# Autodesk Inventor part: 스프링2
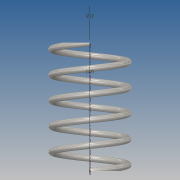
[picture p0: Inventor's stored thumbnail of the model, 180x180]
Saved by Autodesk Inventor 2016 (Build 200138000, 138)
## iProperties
Created: 2016-01
Part Number: 스프링2
Material: 스테인레스 스틸
Document SubType Name: Modeling
Designer: Administrator
Density: 8 g/cm^3
Appearance: 반연마
Mass: 8.55991 g
Surface Area: 21.737 cm^2
Volume: 1.06999 cm^3
Author: Administrator
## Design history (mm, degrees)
sketch "스케치1"
  geometry: L1 (0, 0)-(11, 0); L2 (11, 0)-(11, 31.317); L3 (11, 31.317)-(0, 31.317); L4 (0, 31.317)-(0, 0); C1 r 1 at (11, 0)
  constraints: 8 end point, 2 parallel, 1 centre point, 1 coincident, 1 horizontal, 1 perpendicular
  dimensions: "d0" = 2 diameter of C1; "d1" = 31.3168 distance of L1.end L2.end (derived); "d2" = 22 diameter of L2 L4
feature "코일1" pitch "d3" = 10; turns "d5" = 5; dims "d4" = 31.3168 (= d1), "d6" = 0, angle "d7" = 90 deg, angle "d8" = 90 deg, "d9" = 0, "d10" = 0
sketch "스케치2"
  geometry: L1 (5.3, 0)-(-21.597, 0); L2 (-21.597, 0)-(-21.597, -10.619); L3 (-21.597, -10.619)-(5.3, -10.619); L4 (5.3, -10.619)-(5.3, 0); 3 further points
  constraints: 8 end point, 2 parallel, 1 horizontal, 1 horizontal alignment, 1 perpendicular, 1 point on line
extrude "돌출1" cut sketch "스케치2" stored distance "d11" = 0; taper "d12" = 0 deg
sketch "스케치3"
  geometry: L1 (-4.261, 0)-(22.454, 0); L2 (22.454, 0)-(22.454, 6.999); L3 (22.454, 6.999)-(-4.261, 6.999); L4 (-4.261, 6.999)-(-4.261, 0); 3 further points
  constraints: 8 end point, 2 parallel, 1 horizontal, 1 horizontal alignment, 1 perpendicular, 1 point on line
extrude "돌출2" cut sketch "스케치3" stored distance "d13" = 0; taper "d14" = 0 deg
node "솔리드1"
